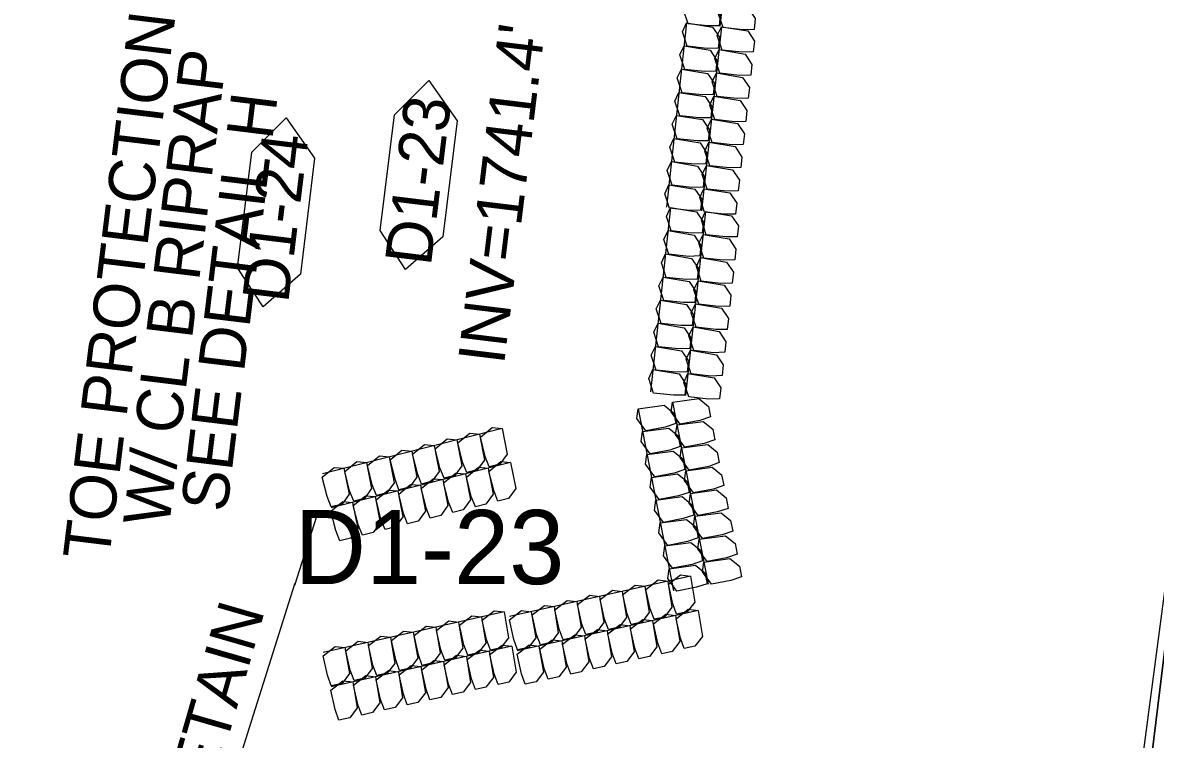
# Model space of a CAD drawing. Extents: x 465700 to 483515, y 488970 to 507540.
# Drawn here: x 481109.3 to 481231.5, y 490264.2 to 490341.6 of the extents above; entities that cross this region are included whole.
import ezdxf

# ---------------------------------------------------------------- set-up
doc = ezdxf.new("R2010")
doc.units = 0
for name, color, linetype in [('Exist Plan Preparation Watershed Blue', 7, 'Continuous'), ('Prop Drainage Structure Box Number Symbol CELL', 7, 'Continuous'), ('Prop Drainage Structure Pipe Plug Label', 7, 'Continuous'), ('Prop Drainage Structure Pipe Stub Out CELL', 7, 'Continuous'), ('Prop Erosion Embankment Toe Protection CELL', 7, 'Continuous'), ('Prop Erosion Embankment Toe Protection Label', 7, 'Continuous'), ('Scratch_Level_4', 7, 'Continuous'), ('Scratch_Level_8', 7, 'Continuous')]:
    doc.layers.add(name, color=color, linetype=linetype)

msp = doc.modelspace()

# ---------------------------------------------------------------- linework, layer by layer
at = {"layer": 'Exist Plan Preparation Watershed Blue'}
for points in [[(481178.35, 489921.07), (481181.18, 489944.23), (481192.1, 489942.89), (481199.42, 490002.85), (481223.67, 490201.37), (481232.65, 490274.58), (481301.55, 490839.02), (481357.88, 490832.14), (481339.74, 490683.62), (481315.49, 490485.09), (481303.36, 490385.83), (481279.12, 490187.3), (481254.87, 489988.78), (481242.75, 489889.52)], [(480982.54, 490200.49), (481022.64, 490226.93), (481057.88, 490239.62), (481085.68, 490250.52), (481125.08, 490261.61), (481159, 490262.25), (481229.67, 490258.2), (481254.1, 490443.2), (481288.29, 490738.89), (481339.74, 490683.62), (481381.2, 490650.46), (481429.31, 490629.05), (481609.7, 490592.3), (481802.24, 490660.02), (481819.54, 490679.79), (481842.61, 490718.46), (481669.68, 490775.55), (481613.6, 490791.65)]]:
    msp.add_lwpolyline(points, dxfattribs=at)
msp.add_lwpolyline([(481241.45, 490191.91), (481273.35, 490227.27), (481291.24, 490286.57), (481303.36, 490385.83), (481311.9, 490453.82), (481327.61, 490584.35), (481339.74, 490683.62), (481353.35, 490795.1), (481357.83, 490831.75), (481325.41, 490836.1), (481323.3, 490836.37), (481263.76, 490349.7), (481254.45, 490271.98), (481232.65, 490274.58), (481223.67, 490201.37)], close=True, dxfattribs=at)
at = {"layer": 'Prop Drainage Structure Box Number Symbol CELL'}
msp.add_lwpolyline([(481147.87, 490319.16), (481149.4, 490331.67), (481153.11, 490335.35), (481156.18, 490331), (481154.65, 490318.49), (481150.62, 490314.95), (481147.87, 490319.16)], dxfattribs=at)
at = {"layer": 'Prop Drainage Structure Pipe Stub Out CELL'}
msp.add_line((481138.61, 490281), (481138.61, 490281), dxfattribs=at)
msp.add_line((481138.61, 490281), (481138.61, 490281), dxfattribs=at)
msp.add_lwpolyline([(481138.62, 490281), (481138.6, 490280.99), (481138.59, 490281), (481138.61, 490281.02), (481138.62, 490281)], dxfattribs=at)
at = {"layer": 'Prop Erosion Embankment Toe Protection CELL'}
for p, q in [((481186.71, 490361.09), (481184.54, 490341.21)), ((481180.94, 490341.59), (481178.78, 490321.7)), ((481184.72, 490341.17), (481182.56, 490321.29)), ((481179.22, 490321.64), (481177.05, 490301.76)), ((481182.99, 490321.23), (481180.83, 490301.35)), ((481179.44, 490300.64), (481183.26, 490281.01)), ((481175.71, 490299.92), (481179.53, 490280.28)), ((481181.35, 490281.87), (481161.84, 490277.5)), ((481161.25, 490278), (481141.73, 490273.63)), ((481182.18, 490278.16), (481162.67, 490273.79)), ((481162.08, 490274.29), (481142.56, 490269.92))]:
    msp.add_line(p, q, dxfattribs=at)
for points in [[(481184.45, 490341.27), (481183.24, 490341.25), (481181.1, 490341.48), (481180.57, 490343.05), (481181.03, 490344.01), (481183.84, 490343.55), (481184.58, 490342.46), (481184.45, 490341.27)], [(481188.23, 490340.86), (481187.02, 490340.84), (481184.88, 490341.07), (481184.35, 490342.64), (481184.8, 490343.6), (481187.62, 490343.14), (481188.36, 490342.05), (481188.23, 490340.86)], [(481184.37, 490338.85), (481183.16, 490338.83), (481181.02, 490339.06), (481180.49, 490340.63), (481180.94, 490341.59), (481183.76, 490341.13), (481184.49, 490340.02), (481184.37, 490338.85)], [(481188.14, 490338.44), (481186.93, 490338.42), (481184.8, 490338.65), (481184.26, 490340.22), (481184.72, 490341.17), (481187.54, 490340.72), (481188.27, 490339.61), (481188.14, 490338.44)], [(481184.09, 490336.36), (481182.88, 490336.32), (481180.75, 490336.55), (481180.21, 490338.14), (481180.67, 490339.1), (481183.49, 490338.62), (481184.22, 490337.51), (481184.09, 490336.36)], [(481187.87, 490335.95), (481186.66, 490335.91), (481184.52, 490336.14), (481183.99, 490337.73), (481184.45, 490338.69), (481187.26, 490338.21), (481188, 490337.1), (481187.87, 490335.95)], [(481183.82, 490333.85), (481182.61, 490333.81), (481180.47, 490334.04), (481179.94, 490335.63), (481180.4, 490336.59), (481183.21, 490336.11), (481183.95, 490335.02), (481183.82, 490333.85)], [(481187.6, 490333.44), (481186.39, 490333.4), (481184.25, 490333.63), (481183.72, 490335.22), (481184.18, 490336.18), (481186.99, 490335.7), (481187.73, 490334.61), (481187.6, 490333.44)], [(481183.55, 490331.34), (481182.34, 490331.32), (481180.2, 490331.56), (481179.67, 490333.12), (481180.12, 490334.08), (481182.94, 490333.62), (481183.68, 490332.54), (481183.55, 490331.34)], [(481187.33, 490330.93), (481186.12, 490330.91), (481183.98, 490331.15), (481183.45, 490332.71), (481183.9, 490333.67), (481186.72, 490333.21), (481187.46, 490332.13), (481187.33, 490330.93)], [(481183.28, 490328.86), (481182.07, 490328.84), (481179.93, 490329.07), (481179.4, 490330.64), (481179.85, 490331.59), (481182.67, 490331.14), (481183.41, 490330.03), (481183.28, 490328.86)], [(481187.06, 490328.45), (481185.85, 490328.43), (481183.71, 490328.66), (481183.18, 490330.23), (481183.63, 490331.18), (481186.45, 490330.73), (481187.18, 490329.62), (481187.06, 490328.45)], [(481183.01, 490326.37), (481181.8, 490326.33), (481179.66, 490326.56), (481179.13, 490328.15), (481179.58, 490329.11), (481182.4, 490328.63), (481183.13, 490327.52), (481183.01, 490326.37)], [(481186.79, 490325.96), (481185.57, 490325.92), (481183.44, 490326.15), (481182.91, 490327.74), (481183.36, 490328.7), (481186.18, 490328.22), (481186.91, 490327.1), (481186.79, 490325.96)], [(481182.73, 490323.86), (481181.52, 490323.82), (481179.38, 490324.05), (481178.85, 490325.64), (481179.31, 490326.6), (481182.12, 490326.12), (481182.86, 490325.03), (481182.73, 490323.86)], [(481186.51, 490323.45), (481185.3, 490323.41), (481183.16, 490323.64), (481182.63, 490325.23), (481183.09, 490326.19), (481185.9, 490325.71), (481186.64, 490324.62), (481186.51, 490323.45)], [(481182.46, 490321.35), (481181.25, 490321.33), (481179.11, 490321.57), (481178.58, 490323.13), (481179.04, 490324.09), (481181.85, 490323.63), (481182.59, 490322.55), (481182.46, 490321.35)], [(481186.24, 490320.94), (481185.03, 490320.92), (481182.89, 490321.15), (481182.36, 490322.72), (481182.81, 490323.68), (481185.63, 490323.22), (481186.37, 490322.13), (481186.24, 490320.94)], [(481182.64, 490318.91), (481181.43, 490318.89), (481179.29, 490319.12), (481178.76, 490320.69), (481179.22, 490321.64), (481182.03, 490321.19), (481182.77, 490320.07), (481182.64, 490318.91)], [(481186.42, 490318.49), (481185.21, 490318.48), (481183.07, 490318.71), (481182.54, 490320.28), (481182.99, 490321.23), (481185.81, 490320.77), (481186.55, 490319.66), (481186.42, 490318.49)], [(481182.37, 490316.42), (481181.16, 490316.38), (481179.02, 490316.61), (481178.49, 490318.2), (481178.95, 490319.16), (481181.76, 490318.67), (481182.5, 490317.56), (481182.37, 490316.42)], [(481186.15, 490316.01), (481184.94, 490315.97), (481182.8, 490316.2), (481182.27, 490317.79), (481182.72, 490318.75), (481185.54, 490318.26), (481186.27, 490317.15), (481186.15, 490316.01)], [(481182.1, 490313.91), (481180.89, 490313.87), (481178.75, 490314.1), (481178.22, 490315.69), (481178.67, 490316.65), (481181.49, 490316.16), (481182.22, 490315.08), (481182.1, 490313.91)], [(481185.88, 490313.5), (481184.66, 490313.46), (481182.53, 490313.69), (481182, 490315.28), (481182.45, 490316.24), (481185.27, 490315.75), (481186, 490314.67), (481185.88, 490313.5)], [(481181.82, 490311.4), (481180.62, 490311.38), (481178.48, 490311.61), (481177.94, 490313.18), (481178.4, 490314.14), (481181.22, 490313.68), (481181.95, 490312.59), (481181.82, 490311.4)], [(481185.6, 490310.99), (481184.39, 490310.97), (481182.26, 490311.2), (481181.72, 490312.77), (481182.18, 490313.73), (481184.99, 490313.27), (481185.73, 490312.18), (481185.6, 490310.99)], [(481181.55, 490308.91), (481180.34, 490308.9), (481178.21, 490309.13), (481177.67, 490310.7), (481178.13, 490311.65), (481180.95, 490311.19), (481181.68, 490310.08), (481181.55, 490308.91)], [(481185.33, 490308.5), (481184.12, 490308.48), (481181.98, 490308.72), (481181.45, 490310.28), (481181.91, 490311.24), (481184.72, 490310.78), (481185.46, 490309.67), (481185.33, 490308.5)], [(481181.28, 490306.43), (481180.07, 490306.39), (481177.93, 490306.62), (481177.4, 490308.21), (481177.86, 490309.17), (481180.67, 490308.68), (481181.41, 490307.57), (481181.28, 490306.43)], [(481185.06, 490306.02), (481183.85, 490305.97), (481181.71, 490306.21), (481181.18, 490307.8), (481181.64, 490308.76), (481184.45, 490308.27), (481185.19, 490307.16), (481185.06, 490306.02)], [(481181.01, 490303.92), (481179.8, 490303.88), (481177.66, 490304.11), (481177.13, 490305.7), (481177.59, 490306.66), (481180.4, 490306.17), (481181.14, 490305.09), (481181.01, 490303.92)], [(481184.79, 490303.51), (481183.58, 490303.46), (481181.44, 490303.7), (481180.91, 490305.29), (481181.36, 490306.24), (481184.18, 490305.76), (481184.91, 490304.68), (481184.79, 490303.51)], [(481180.74, 490301.41), (481179.53, 490301.39), (481177.39, 490301.62), (481176.86, 490303.19), (481177.31, 490304.15), (481180.13, 490303.69), (481180.87, 490302.6), (481180.74, 490301.41)], [(481184.51, 490301), (481183.31, 490300.98), (481181.17, 490301.21), (481180.63, 490302.78), (481181.09, 490303.73), (481183.91, 490303.28), (481184.64, 490302.19), (481184.51, 490301)], [(481179.79, 490298.32), (481178.64, 490297.94), (481176.53, 490297.53), (481175.56, 490298.87), (481175.71, 490299.92), (481178.54, 490300.31), (481179.57, 490299.47), (481179.79, 490298.32)], [(481183.52, 490299.04), (481182.37, 490298.67), (481180.26, 490298.25), (481179.29, 490299.59), (481179.44, 490300.64), (481182.27, 490301.04), (481183.3, 490300.19), (481183.52, 490299.04)], [(481180.27, 490295.86), (481179.12, 490295.46), (481177.01, 490295.05), (481176.03, 490296.41), (481176.19, 490297.46), (481179.02, 490297.83), (481180.05, 490296.99), (481180.27, 490295.86)], [(481184, 490296.59), (481182.85, 490296.19), (481180.74, 490295.78), (481179.76, 490297.14), (481179.92, 490298.19), (481182.75, 490298.56), (481183.78, 490297.72), (481184, 490296.59)], [(481180.75, 490293.38), (481179.61, 490292.98), (481177.5, 490292.57), (481176.52, 490293.93), (481176.67, 490294.98), (481179.5, 490295.36), (481180.53, 490294.54), (481180.75, 490293.38)], [(481184.48, 490294.11), (481183.34, 490293.71), (481181.23, 490293.3), (481180.25, 490294.66), (481180.4, 490295.71), (481183.23, 490296.08), (481184.26, 490295.26), (481184.48, 490294.11)], [(481181.23, 490290.9), (481180.08, 490290.53), (481177.97, 490290.12), (481177, 490291.46), (481177.15, 490292.5), (481179.98, 490292.9), (481181, 490292.08), (481181.23, 490290.9)], [(481184.96, 490291.63), (481183.81, 490291.25), (481181.7, 490290.84), (481180.73, 490292.18), (481180.88, 490293.23), (481183.71, 490293.63), (481184.73, 490292.81), (481184.96, 490291.63)], [(481181.71, 490288.45), (481180.56, 490288.07), (481178.45, 490287.66), (481177.48, 490289), (481177.63, 490290.05), (481180.46, 490290.45), (481181.49, 490289.6), (481181.71, 490288.45)], [(481185.44, 490289.18), (481184.29, 490288.8), (481182.18, 490288.39), (481181.21, 490289.73), (481181.36, 490290.78), (481184.19, 490291.17), (481185.22, 490290.33), (481185.44, 490289.18)], [(481185.92, 490286.72), (481184.77, 490286.32), (481182.66, 490285.91), (481181.68, 490287.27), (481181.84, 490288.32), (481184.67, 490288.7), (481185.7, 490287.85), (481185.92, 490286.72)], [(481182.19, 490286), (481181.04, 490285.6), (481178.93, 490285.18), (481177.95, 490286.55), (481178.11, 490287.6), (481180.94, 490287.97), (481181.97, 490287.13), (481182.19, 490286)], [(481186.4, 490284.24), (481185.26, 490283.84), (481183.15, 490283.43), (481182.17, 490284.8), (481182.32, 490285.84), (481185.15, 490286.22), (481186.18, 490285.4), (481186.4, 490284.24)], [(481182.67, 490283.52), (481181.53, 490283.12), (481179.42, 490282.71), (481178.44, 490284.07), (481178.59, 490285.12), (481181.42, 490285.49), (481182.45, 490284.67), (481182.67, 490283.52)], [(481186.88, 490281.77), (481185.73, 490281.39), (481183.62, 490280.98), (481182.65, 490282.32), (481182.8, 490283.37), (481185.63, 490283.76), (481186.65, 490282.94), (481186.88, 490281.77)], [(481183.15, 490281.04), (481182, 490280.66), (481179.89, 490280.25), (481178.92, 490281.59), (481179.07, 490282.64), (481181.9, 490283.04), (481182.92, 490282.22), (481183.15, 490281.04)], [(481179.87, 490277.75), (481179.46, 490278.88), (481178.99, 490280.98), (481180.3, 490281.99), (481181.35, 490281.87), (481181.83, 490279.06), (481181.02, 490278), (481179.87, 490277.75)], [(481174.97, 490276.65), (481174.53, 490277.78), (481174.06, 490279.88), (481175.4, 490280.89), (481176.45, 490280.77), (481176.9, 490277.95), (481176.11, 490276.9), (481174.97, 490276.65)], [(481177.43, 490277.2), (481177, 490278.33), (481176.53, 490280.43), (481177.86, 490281.45), (481178.91, 490281.32), (481179.37, 490278.5), (481178.55, 490277.45), (481177.43, 490277.2)], [(481170.06, 490275.55), (481169.65, 490276.69), (481169.18, 490278.79), (481170.49, 490279.8), (481171.55, 490279.67), (481172.02, 490276.86), (481171.21, 490275.81), (481170.06, 490275.55)], [(481172.5, 490276.1), (481172.09, 490277.23), (481171.62, 490279.33), (481172.93, 490280.34), (481173.99, 490280.22), (481174.46, 490277.41), (481173.67, 490276.36), (481172.5, 490276.1)], [(481165.16, 490274.45), (481164.73, 490275.58), (481164.26, 490277.68), (481165.59, 490278.7), (481166.64, 490278.58), (481167.1, 490275.76), (481166.31, 490274.71), (481165.16, 490274.45)], [(481167.62, 490275), (481167.19, 490276.14), (481166.72, 490278.23), (481168.06, 490279.25), (481169.11, 490279.13), (481169.56, 490276.31), (481168.75, 490275.25), (481167.62, 490275)], [(481180.7, 490274.04), (481180.29, 490275.18), (481179.82, 490277.27), (481181.13, 490278.28), (481182.18, 490278.16), (481182.66, 490275.35), (481181.85, 490274.29), (481180.7, 490274.04)], [(481154.86, 490272.78), (481154.43, 490273.91), (481153.96, 490276.01), (481155.29, 490277.03), (481156.34, 490276.9), (481156.8, 490274.08), (481156.01, 490273.04), (481154.86, 490272.78)], [(481157.32, 490273.33), (481156.89, 490274.46), (481156.42, 490276.56), (481157.75, 490277.58), (481158.81, 490277.46), (481159.26, 490274.64), (481158.45, 490273.58), (481157.32, 490273.33)], [(481159.76, 490273.88), (481159.35, 490275.02), (481158.88, 490277.11), (481160.19, 490278.12), (481161.25, 490278), (481161.72, 490275.19), (481160.91, 490274.13), (481159.76, 490273.88)], [(481162.7, 490273.9), (481162.29, 490275.04), (481161.82, 490277.14), (481163.13, 490278.15), (481164.18, 490278.02), (481164.66, 490275.21), (481163.87, 490274.16), (481162.7, 490273.9)], [(481175.8, 490272.94), (481175.36, 490274.07), (481174.89, 490276.17), (481176.23, 490277.19), (481177.28, 490277.06), (481177.73, 490274.24), (481176.94, 490273.2), (481175.8, 490272.94)], [(481178.26, 490273.49), (481177.83, 490274.62), (481177.36, 490276.72), (481178.69, 490277.74), (481179.75, 490277.62), (481180.2, 490274.8), (481179.38, 490273.74), (481178.26, 490273.49)], [(481149.96, 490271.68), (481149.55, 490272.82), (481149.08, 490274.92), (481150.39, 490275.93), (481151.44, 490275.81), (481151.92, 490272.99), (481151.1, 490271.94), (481149.96, 490271.68)], [(481152.39, 490272.23), (481151.99, 490273.37), (481151.52, 490275.46), (481152.83, 490276.47), (481153.88, 490276.35), (481154.36, 490273.54), (481153.57, 490272.49), (481152.39, 490272.23)], [(481170.89, 490271.84), (481170.48, 490272.98), (481170.01, 490275.08), (481171.33, 490276.09), (481172.38, 490275.97), (481172.85, 490273.15), (481172.04, 490272.1), (481170.89, 490271.84)], [(481173.33, 490272.39), (481172.92, 490273.53), (481172.45, 490275.62), (481173.76, 490276.63), (481174.82, 490276.51), (481175.29, 490273.7), (481174.5, 490272.65), (481173.33, 490272.39)], [(481145.05, 490270.58), (481144.62, 490271.72), (481144.15, 490273.81), (481145.48, 490274.83), (481146.54, 490274.71), (481146.99, 490271.89), (481146.2, 490270.84), (481145.05, 490270.58)], [(481147.52, 490271.13), (481147.08, 490272.27), (481146.61, 490274.37), (481147.95, 490275.38), (481149, 490275.26), (481149.45, 490272.44), (481148.64, 490271.39), (481147.52, 490271.13)], [(481165.99, 490270.74), (481165.56, 490271.88), (481165.09, 490273.97), (481166.42, 490274.99), (481167.47, 490274.87), (481167.93, 490272.05), (481167.14, 490271), (481165.99, 490270.74)], [(481168.45, 490271.29), (481168.02, 490272.43), (481167.55, 490274.53), (481168.89, 490275.54), (481169.94, 490275.42), (481170.39, 490272.6), (481169.58, 490271.55), (481168.45, 490271.29)], [(481142.59, 490270.03), (481142.18, 490271.17), (481141.71, 490273.27), (481143.02, 490274.28), (481144.07, 490274.15), (481144.55, 490271.34), (481143.76, 490270.29), (481142.59, 490270.03)], [(481155.69, 490269.07), (481155.26, 490270.2), (481154.79, 490272.3), (481156.12, 490273.32), (481157.17, 490273.2), (481157.63, 490270.38), (481156.84, 490269.33), (481155.69, 490269.07)], [(481158.15, 490269.62), (481157.72, 490270.76), (481157.25, 490272.85), (481158.59, 490273.87), (481159.64, 490273.75), (481160.09, 490270.93), (481159.28, 490269.87), (481158.15, 490269.62)], [(481160.59, 490270.17), (481160.18, 490271.31), (481159.71, 490273.41), (481161.03, 490274.42), (481162.08, 490274.29), (481162.55, 490271.48), (481161.74, 490270.43), (481160.59, 490270.17)], [(481163.53, 490270.19), (481163.12, 490271.33), (481162.65, 490273.43), (481163.96, 490274.44), (481165.01, 490274.32), (481165.49, 490271.5), (481164.7, 490270.45), (481163.53, 490270.19)], [(481150.79, 490267.97), (481150.38, 490269.11), (481149.91, 490271.21), (481151.22, 490272.22), (481152.27, 490272.1), (481152.75, 490269.28), (481151.93, 490268.23), (481150.79, 490267.97)], [(481153.23, 490268.52), (481152.82, 490269.66), (481152.35, 490271.76), (481153.66, 490272.77), (481154.71, 490272.64), (481155.19, 490269.83), (481154.4, 490268.78), (481153.23, 490268.52)], [(481145.88, 490266.87), (481145.45, 490268.01), (481144.98, 490270.11), (481146.31, 490271.12), (481147.37, 490271), (481147.82, 490268.18), (481147.03, 490267.13), (481145.88, 490266.87)], [(481148.35, 490267.43), (481147.91, 490268.56), (481147.44, 490270.66), (481148.78, 490271.67), (481149.83, 490271.55), (481150.28, 490268.73), (481149.47, 490267.68), (481148.35, 490267.43)], [(481143.42, 490266.32), (481143.01, 490267.46), (481142.54, 490269.56), (481143.85, 490270.57), (481144.9, 490270.45), (481145.38, 490267.63), (481144.59, 490266.58), (481143.42, 490266.32)]]:
    msp.add_lwpolyline(points, dxfattribs=at)
at = {"layer": 'Scratch_Level_4'}
for p, q in [((481161.02, 490297.81), (481141.63, 490292.92)), ((481161.95, 490294.12), (481142.56, 490289.24)), ((481138.64, 490280.87), (481141.04, 490288.33))]:
    msp.add_line(p, q, dxfattribs=at)
for points in [[(481132.47, 490315.13), (481134, 490327.64), (481137.71, 490331.32), (481140.78, 490326.97), (481139.25, 490314.46), (481135.22, 490310.92), (481132.47, 490315.13)], [(481159.65, 490293.65), (481159.21, 490294.77), (481158.69, 490296.86), (481159.97, 490297.9), (481161.02, 490297.81), (481161.58, 490295.01), (481160.79, 490293.93), (481159.65, 490293.65)], [(481154.78, 490292.42), (481154.31, 490293.54), (481153.79, 490295.62), (481155.1, 490296.68), (481156.15, 490296.58), (481156.68, 490293.77), (481155.92, 490292.71), (481154.78, 490292.42)], [(481157.23, 490293.04), (481156.76, 490294.16), (481156.24, 490296.24), (481157.54, 490297.29), (481158.6, 490297.2), (481159.13, 490294.39), (481158.34, 490293.32), (481157.23, 490293.04)], [(481149.9, 490291.19), (481149.47, 490292.32), (481148.94, 490294.4), (481150.22, 490295.45), (481151.28, 490295.35), (481151.83, 490292.55), (481151.04, 490291.48), (481149.9, 490291.19)], [(481152.33, 490291.8), (481151.89, 490292.93), (481151.36, 490295.01), (481152.65, 490296.06), (481153.7, 490295.96), (481154.25, 490293.16), (481153.49, 490292.1), (481152.33, 490291.8)], [(481145.03, 490289.96), (481144.57, 490291.08), (481144.04, 490293.17), (481145.35, 490294.22), (481146.41, 490294.13), (481146.93, 490291.32), (481146.17, 490290.25), (481145.03, 490289.96)], [(481147.48, 490290.58), (481147.02, 490291.7), (481146.49, 490293.79), (481147.8, 490294.84), (481148.85, 490294.74), (481149.38, 490291.94), (481148.6, 490290.86), (481147.48, 490290.58)], [(481160.58, 490289.96), (481160.14, 490291.09), (481159.61, 490293.17), (481160.9, 490294.22), (481161.95, 490294.12), (481162.5, 490291.32), (481161.72, 490290.25), (481160.58, 490289.96)], [(481142.58, 490289.35), (481142.14, 490290.47), (481141.62, 490292.56), (481142.9, 490293.6), (481143.96, 490293.51), (481144.51, 490290.71), (481143.75, 490289.64), (481142.58, 490289.35)], [(481155.71, 490288.73), (481155.24, 490289.85), (481154.72, 490291.94), (481156.02, 490292.99), (481157.08, 490292.9), (481157.61, 490290.09), (481156.84, 490289.02), (481155.71, 490288.73)], [(481158.15, 490289.35), (481157.69, 490290.47), (481157.17, 490292.56), (481158.47, 490293.61), (481159.53, 490293.51), (481160.06, 490290.71), (481159.27, 490289.63), (481158.15, 490289.35)], [(481150.83, 490287.51), (481150.39, 490288.63), (481149.87, 490290.72), (481151.15, 490291.76), (481152.21, 490291.67), (481152.76, 490288.87), (481151.97, 490287.79), (481150.83, 490287.51)], [(481153.26, 490288.12), (481152.82, 490289.24), (481152.29, 490291.33), (481153.58, 490292.37), (481154.63, 490292.28), (481155.18, 490289.48), (481154.42, 490288.41), (481153.26, 490288.12)], [(481145.96, 490286.28), (481145.5, 490287.4), (481144.97, 490289.48), (481146.28, 490290.54), (481147.33, 490290.44), (481147.86, 490287.63), (481147.1, 490286.57), (481145.96, 490286.28)], [(481148.41, 490286.9), (481147.95, 490288.02), (481147.42, 490290.1), (481148.73, 490291.15), (481149.78, 490291.06), (481150.31, 490288.25), (481149.52, 490287.18), (481148.41, 490286.9)], [(481143.51, 490285.66), (481143.07, 490286.79), (481142.55, 490288.87), (481143.83, 490289.92), (481144.89, 490289.82), (481145.44, 490287.02), (481144.67, 490285.95), (481143.51, 490285.66)]]:
    msp.add_lwpolyline(points, dxfattribs=at)
at = {"layer": 'Scratch_Level_8'}
msp.add_line((481138.61, 490281), (481123.8, 490233.91), dxfattribs=at)

# ---------------------------------------------------------------- texts
at = {"layer": 'Prop Drainage Structure Box Number Symbol CELL'}
msp.add_text('D1-23', height=5, rotation=83.0394, dxfattribs=at).set_placement((481153.33, 490315.24))
at = {"layer": 'Prop Drainage Structure Pipe Plug Label'}
msp.add_text('RETAIN', height=5, rotation=73.9057, dxfattribs=at).set_placement((481128.64, 490254.58))
at = {"layer": 'Prop Drainage Structure Pipe Stub Out CELL'}
msp.add_text('SO', height=0.0104, rotation=173.0365, dxfattribs=at).set_placement((481138.61, 490281.01))
at = {"layer": 'Prop Erosion Embankment Toe Protection Label'}
for s, p in [('TOE PROTECTION', (481118.58, 490283.44)), ('W/ CL B RIPRAP', (481125.07, 490287.09)), ('SEE DETAIL H', (481131.31, 490288.67))]:
    msp.add_text(s, height=5, rotation=83.0365, dxfattribs=at).set_placement(p)
at = {"layer": 'Scratch_Level_4'}
for s, p in [("INV=1741.4'", (481161.23, 490304.59)), ('D1-24', (481137.93, 490311.24))]:
    msp.add_text(s, height=5, rotation=83.0394, dxfattribs=at).set_placement(p)
at = {"layer": 'Scratch_Level_8'}
msp.add_text('D1-23', height=8, dxfattribs=at).set_placement((481138.61, 490281))

doc.saveas('drawing.dxf')
